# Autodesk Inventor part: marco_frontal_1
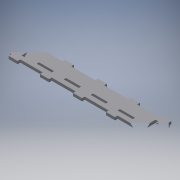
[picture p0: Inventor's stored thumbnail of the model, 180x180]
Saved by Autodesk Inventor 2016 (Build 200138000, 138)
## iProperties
Created: 2017-06
Part Number: marco_frontal_1
Material: Generic
Document SubType Name: Modeling
Designer: laboratorioesan
Density: 1 g/cm^3
Appearance: Default
Author: laboratorioesan
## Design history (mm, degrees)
sketch "Sketch1"
  geometry: L1 (440, 0)-(440, 15.5) reference; L2 (440, 15.5)-(540, 15.5) reference; L3 (540, 15.5)-(540, 0) reference; L4 (540, 0)-(440, 0) reference; L5 (80, 0)-(80, 15.5) reference; L6 (80, 15.5)-(180, 15.5) reference; L7 (180, 15.5)-(180, 0) reference; L8 (180, 0)-(80, 0) reference; L9 (260, 0)-(260, 15.5) reference; L10 (260, 15.5)-(360, 15.5) reference; L11 (360, 15.5)-(360, 0) reference; L12 (360, 0)-(260, 0) reference; L13 (620, 0)-(620, 15.5) reference; L14 (620, 15.5)-(720, 15.5) reference; L15 (720, 15.5)-(720, 0) reference; L16 (720, 0)-(620, 0) reference; L17 (-18.5, -2.5)-(-18.5, 72.5) reference; L18 (-18.5, 72.5)-(0, 72.5) reference; L19 (0, 72.5)-(0, -2.5) reference; L20 (0, -2.5)-(-18.5, -2.5) reference; L21 (818.5, -2.5)-(800, -2.5) reference; L22 (800, -2.5)-(800, 72.5) reference; L23 (800, 72.5)-(818.5, 72.5) reference; L24 (818.5, 72.5)-(818.5, -2.5) reference; L25 (-38.5, -30)-(838.5, -30) reference; L26 (838.5, -30)-(838.5, 100) reference; L27 (838.5, 100)-(-38.5, 100) reference; L28 (-38.5, 100)-(-38.5, -30) reference; L29 (440, 0)-(440, 15.5) reference; L30 (440, 15.5)-(540, 15.5) reference; L31 (540, 15.5)-(540, 0) reference; L32 (540, 0)-(440, 0) reference; L33 (80, 0)-(80, 15.5) reference; L34 (80, 15.5)-(180, 15.5) reference; L35 (180, 15.5)-(180, 0) reference; L36 (180, 0)-(80, 0) reference; L37 (260, 0)-(260, 15.5) reference; L38 (260, 15.5)-(360, 15.5) reference; L39 (360, 15.5)-(360, 0) reference; L40 (360, 0)-(260, 0) reference; L41 (620, 0)-(620, 15.5) reference; L42 (620, 15.5)-(720, 15.5) reference; L43 (720, 15.5)-(720, 0) reference; L44 (720, 0)-(620, 0) reference; L45 (-18.5, -2.5)-(-18.5, 72.5) reference; L46 (-18.5, 72.5)-(0, 72.5) reference; L47 (0, 72.5)-(0, -2.5) reference; L48 (0, -2.5)-(-18.5, -2.5) reference; L49 (818.5, -2.5)-(800, -2.5) reference; L50 (800, -2.5)-(800, 72.5) reference; L51 (800, 72.5)-(818.5, 72.5) reference; L52 (818.5, 72.5)-(818.5, -2.5) reference; L53 (-38.5, -30)-(838.5, -30) reference; L54 (838.5, -30)-(838.5, 100) reference; L55 (838.5, 100)-(-38.5, 100) reference; L56 (-38.5, 100)-(-38.5, -30) reference; L57 (892.636, 118.5)-(930, 118.5) reference; L58 (930, 100)-(930, 118.5) reference; L59 (-130, 118.5)-(-130, 100) reference; L60 (-130, 100)-(930, 100); L61 (930, 100)-(930, -30); L62 (930, -30)-(-130, -30); L63 (-130, -30)-(-130, 100); L64 (-60, 100)-(0, 100)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; 2 further points
  constraints: 88 end point, 22 parallel, 15 point on line, 11 horizontal, 11 perpendicular, 4 horizontal alignment, 1 midpoint, 1 vertical alignment
  dimensions: "d0" = 60 distance of L66.end L65.end; "d1" = 18 distance of L65.end L64.end; "d2" = 60 distance of L69.end L70.end; "d3" = 60 distance of L73.end L74.end; "d4" = 60 distance of L77.end L78.end; "d5" = 60 distance of L81.end L82.end; "d6" = 70 distance of L59.end L64.start; "d7" = 150 distance of L70.end L64.end; "d8" = 70 distance of L60.end L81.end; "d9" = 150 distance of L82.end L77.end; "d10" = 160 distance of L78.end L73.end; "d13" = 18 distance of L84.end L85.end
extrude "Extrusion2" new body sketch "Sketch1" distance "d14" = 18.5; taper "d15" = 0 deg
sketch "Sketch2"
  geometry: L1 (620, 0)-(620, 15.5) reference; L2 (620, 15.5)-(720, 15.5) reference; L3 (720, 15.5)-(720, 0) reference; L4 (720, 0)-(620, 0) reference; L5 (260, 0)-(260, 15.5) reference; L6 (260, 15.5)-(360, 15.5) reference; L7 (360, 15.5)-(360, 0) reference; L8 (360, 0)-(260, 0) reference; L9 (80, 0)-(80, 15.5) reference; L10 (80, 15.5)-(180, 15.5) reference; L11 (180, 15.5)-(180, 0) reference; L12 (180, 0)-(80, 0) reference; L13 (440, 0)-(440, 15.5) reference; L14 (440, 15.5)-(540, 15.5) reference; L15 (540, 15.5)-(540, 0) reference; L16 (540, 0)-(440, 0) reference; L17 (818.5, -2.5)-(800, -2.5) reference; L18 (800, -2.5)-(800, 72.5) reference; L19 (800, 72.5)-(818.5, 72.5) reference; L20 (818.5, 72.5)-(818.5, -2.5) reference; L21 (-18.5, -2.5)-(-18.5, 72.5) reference; L22 (-18.5, 72.5)-(0, 72.5) reference; L23 (0, 72.5)-(0, -2.5) reference; L24 (0, -2.5)-(-18.5, -2.5) reference; L25 (150, -30)-(150, -48) reference; L26 (150, -48)-(210, -48) reference; L27 (210, -48)-(210, -30) reference; L28 (210, -30)-(370, -30) reference; L29 (370, -30)-(370, -48) reference; L30 (370, -48)-(430, -48) reference; L31 (430, -48)-(430, -30) reference; L32 (430, -30)-(590, -30) reference; L33 (590, -30)-(590, -48) reference; L34 (590, -48)-(650, -48) reference; L35 (650, -48)-(650, -30) reference; L36 (650, -30)-(800, -30) reference; L37 (800, -30)-(800, -48) reference; L38 (800, -48)-(860, -48) reference; L39 (860, -48)-(860, -30) reference; L40 (860, -30)-(930, -30) reference; L41 (930, -30)-(930, 100) reference; L42 (930, 100)-(860, 100) reference; L43 (860, 100)-(860, 118) reference; L44 (860, 118)-(800, 118) reference; L45 (800, 118)-(800, 100) reference; L46 (800, 100)-(650, 100) reference; L47 (650, 100)-(650, 118) reference; L48 (650, 118)-(590, 118) reference; L49 (590, 118)-(590, 100) reference; L50 (590, 100)-(430, 100) reference; L51 (430, 100)-(430, 118) reference; L52 (430, 118)-(370, 118) reference; L53 (370, 118)-(370, 100) reference; L54 (370, 100)-(210, 100) reference; L55 (210, 100)-(210, 118) reference; L56 (210, 118)-(150, 118) reference; L57 (150, 118)-(150, 100) reference; L58 (150, 100)-(0, 100) reference; L59 (0, 100)-(0, 118) reference; L60 (0, 118)-(-60, 118) reference; L61 (-60, 118)-(-60, 100) reference; L62 (-60, 100)-(-130, 100) reference; L63 (-130, 100)-(-130, -30) reference; L64 (-130, -30)-(-60, -30) reference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; 1 further point
  constraints: 16 end point, 4 parallel, 2 horizontal, 2 midpoint, 2 perpendicular
extrude "Extrusion3" cut sketch "Sketch2" distance "d16" = 18.5; taper "d17" = 0 deg
sketch "Sketch3"
  geometry: L1 (848.5, -30)-(848.5, 100) reference; L2 (895, -30)-(895, 100) reference; L3 (895, 100)-(860, 100) reference; L4 (860, 100)-(860, 118) reference; L5 (860, 118)-(800, 118) reference; L6 (800, 118)-(800, 100) reference; L7 (800, 100)-(650, 100) reference; L8 (650, 100)-(650, 118) reference; L9 (650, 118)-(590, 118) reference; L10 (590, 118)-(590, 100) reference; L11 (590, 100)-(430, 100) reference; L12 (430, 100)-(430, 118) reference; L13 (430, 118)-(370, 118) reference; L14 (370, 118)-(370, 100) reference; L15 (370, 100)-(210, 100) reference; L16 (210, 100)-(210, 118) reference; L17 (210, 118)-(150, 118) reference; L18 (150, 118)-(150, 100) reference; L19 (150, 100)-(0, 100) reference; L20 (0, 100)-(0, 118) reference; L21 (0, 118)-(-60, 118) reference; L22 (-60, 118)-(-60, 100) reference; L23 (-60, 100)-(-95, 100) reference; L24 (-95, 100)-(-95, -30) reference; L25 (-95, -30)-(-60, -30) reference; L26 (-60, -30)-(-60, -48) reference; L27 (-60, -48)-(0, -48) reference; L28 (0, -48)-(0, -30) reference; L29 (0, -30)-(150, -30) reference; L30 (150, -30)-(150, -48) reference; L31 (150, -48)-(210, -48) reference; L32 (210, -48)-(210, -30) reference; L33 (210, -30)-(370, -30) reference; L34 (370, -30)-(370, -48) reference; L35 (370, -48)-(430, -48) reference; L36 (430, -48)-(430, -30) reference; L37 (430, -30)-(590, -30) reference; L38 (590, -30)-(590, -48) reference; L39 (590, -48)-(650, -48) reference; L40 (650, -48)-(650, -30) reference; L41 (650, -30)-(800, -30) reference; L42 (800, -30)-(800, -48) reference; L43 (800, -48)-(860, -48) reference; L44 (860, -48)-(860, -30) reference; L45 (860, -30)-(895, -30) reference; L46 (620, 0)-(620, 15.5) reference; L47 (620, 15.5)-(720, 15.5) reference; L48 (720, 15.5)-(720, 0) reference; L49 (720, 0)-(620, 0) reference; L50 (260, 0)-(260, 15.5) reference; L51 (260, 15.5)-(360, 15.5) reference; L52 (360, 15.5)-(360, 0) reference; L53 (360, 0)-(260, 0) reference; L54 (80, 0)-(80, 15.5) reference; L55 (80, 15.5)-(180, 15.5) reference; L56 (180, 15.5)-(180, 0) reference; L57 (180, 0)-(80, 0) reference; L58 (440, 0)-(440, 15.5) reference; L59 (440, 15.5)-(540, 15.5) reference; L60 (540, 15.5)-(540, 0) reference; L61 (540, 0)-(440, 0) reference; L62 (818.5, -2.5)-(800, -2.5) reference; L63 (800, -2.5)-(800, 72.5) reference; L64 (800, 72.5)-(818.5, 72.5) reference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; 1 further point
  constraints: 16 end point, 4 parallel, 2 horizontal, 2 perpendicular, 2 point on line
  dimensions: "d18" = 15 distance of L73.end L72.end; "d19" = 15 distance of L76.end L77.end
extrude "Extrusion4" cut sketch "Sketch3" distance "d20" = 18.5; taper "d21" = 0 deg
sketch "Sketch4"
  geometry: L1 (-18.5, -2.5)-(-18.5, 72.5) reference; L2 (-18.5, 72.5)-(0, 72.5) reference; L3 (0, 72.5)-(0, -2.5) reference; L4 (0, -2.5)-(-18.5, -2.5) reference; L5 (818.5, -2.5)-(800, -2.5) reference; L6 (800, -2.5)-(800, 72.5) reference; L7 (800, 72.5)-(818.5, 72.5) reference; L8 (818.5, 72.5)-(818.5, -2.5) reference; L9 (440, 0)-(440, 15.5) reference; L10 (440, 15.5)-(540, 15.5) reference; L11 (540, 15.5)-(540, 0) reference; L12 (540, 0)-(440, 0) reference; L13 (80, 0)-(80, 15.5) reference; L14 (80, 15.5)-(180, 15.5) reference; L15 (180, 15.5)-(180, 0) reference; L16 (180, 0)-(80, 0) reference; L17 (260, 0)-(260, 15.5) reference; L18 (260, 15.5)-(360, 15.5) reference; L19 (360, 15.5)-(360, 0) reference; L20 (360, 0)-(260, 0) reference; L21 (620, 0)-(620, 15.5) reference; L22 (620, 15.5)-(720, 15.5) reference; L23 (720, 15.5)-(720, 0) reference; L24 (720, 0)-(620, 0) reference; L25 (880, -30)-(880, 100) reference; L26 (880, 100)-(860, 100) reference; L27 (860, 100)-(860, 118) reference; L28 (860, 118)-(800, 118) reference; L29 (800, 118)-(800, 100) reference; L30 (800, 100)-(650, 100) reference; L31 (650, 100)-(650, 118) reference; L32 (650, 118)-(590, 118) reference; L33 (590, 118)-(590, 100) reference; L34 (590, 100)-(430, 100) reference; L35 (430, 100)-(430, 118) reference; L36 (430, 118)-(370, 118) reference; L37 (370, 118)-(370, 100) reference; L38 (370, 100)-(210, 100) reference; L39 (210, 100)-(210, 118) reference; L40 (210, 118)-(150, 118) reference; L41 (150, 118)-(150, 100) reference; L42 (150, 100)-(0, 100) reference; L43 (0, 100)-(0, 118) reference; L44 (0, 118)-(-60, 118) reference; L45 (-60, 118)-(-60, 100) reference; L46 (-60, 100)-(-80, 100) reference; L47 (-80, 100)-(-80, -30) reference; L48 (-80, -30)-(-60, -30) reference; L49 (-60, -30)-(-60, -48) reference; L50 (-60, -48)-(0, -48) reference; L51 (0, -48)-(0, -30) reference; L52 (0, -30)-(150, -30) reference; L53 (150, -30)-(150, -48) reference; L54 (150, -48)-(210, -48) reference; L55 (210, -48)-(210, -30) reference; L56 (210, -30)-(370, -30) reference; L57 (370, -30)-(370, -48) reference; L58 (370, -48)-(430, -48) reference; L59 (430, -48)-(430, -30) reference; L60 (430, -30)-(590, -30) reference; L61 (590, -30)-(590, -48) reference; L62 (590, -48)-(650, -48) reference; L63 (650, -48)-(650, -30) reference; L64 (650, -30)-(800, -30) reference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; 1 further point
  constraints: 16 end point, 4 parallel, 2 horizontal, 2 midpoint, 2 perpendicular
extrude "Extrusion5" cut sketch "Sketch4" distance "d22" = 18.5; taper "d23" = 0 deg
body "Solid2"
node "Reference1"
node "Reference2"
node "Reference3"
node "Reference4"
node "Reference5"
node "Projected Loop1"
node "Reference6"
node "Projected Loop2"
node "Projected Loop3"
